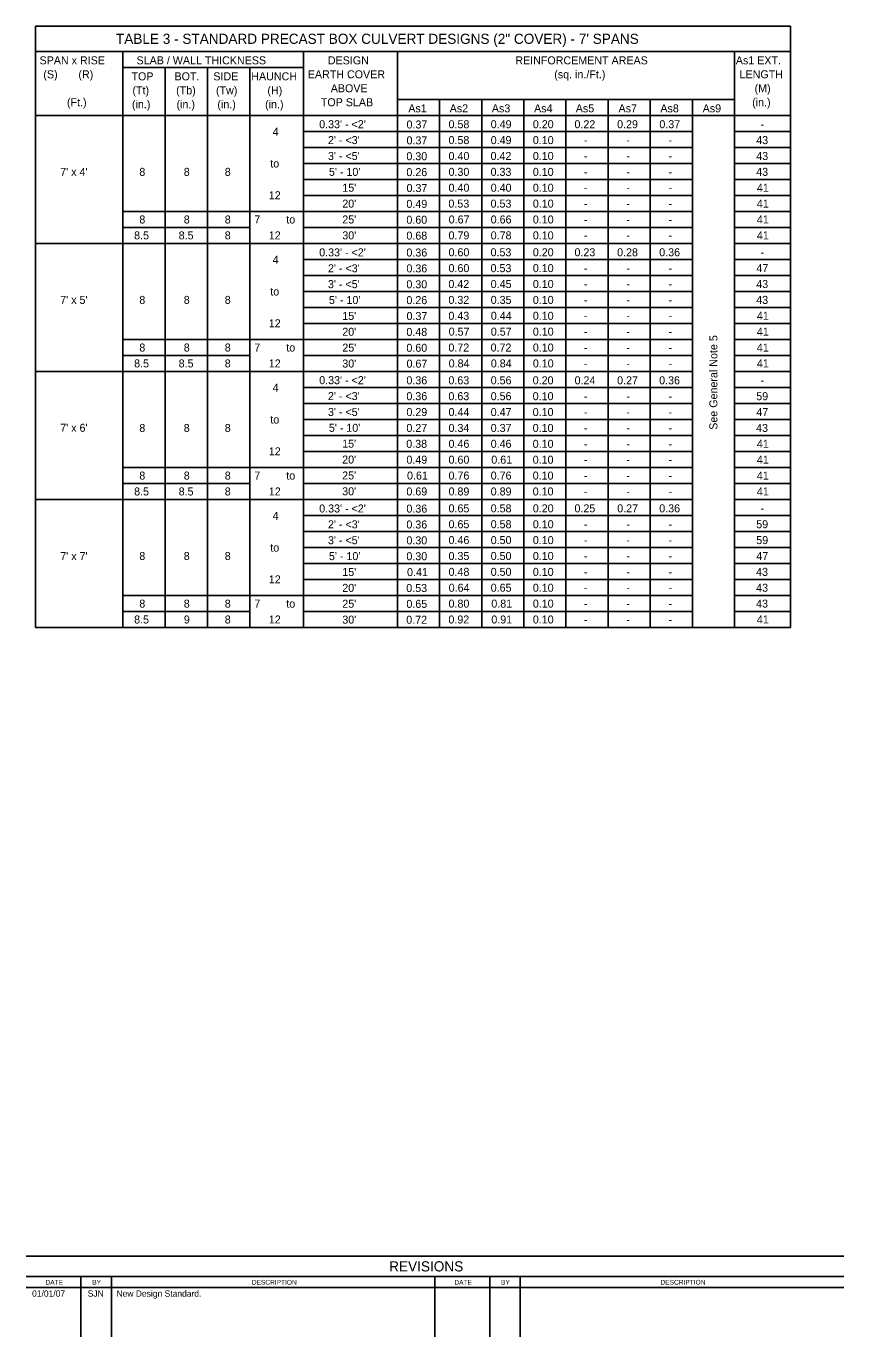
# Model space of a CAD drawing. Extents: x 10342.77 to 10344.98, y 76399.47 to 76400.59.
# Drawn here: x 10342.77 to 10343.414, y 76399.468 to 76400.5 of the extents above; entities that cross this region are included whole.
import ezdxf

# ---------------------------------------------------------------- set-up
doc = ezdxf.new("R2010")
doc.units = 0
for name, color, linetype in [('AdhocPoint_dp', 7, 'Continuous'), ('Border', 7, 'Continuous'), ('PlotBorder_dp', 7, 'Continuous')]:
    doc.layers.add(name, color=color, linetype=linetype)

msp = doc.modelspace()

# ---------------------------------------------------------------- linework, layer by layer
at = {"layer": 'Border'}
for p, q in [((10343.4138, 76399.5314), (10342.7697, 76399.5314)), ((10343.4138, 76399.5153), (10342.7697, 76399.5153)), ((10342.8127, 76399.5153), (10342.8127, 76399.468)), ((10342.8369, 76399.5153), (10342.8369, 76399.468)), ((10343.0917, 76399.5153), (10343.0917, 76399.468)), ((10343.1348, 76399.5153), (10343.1348, 76399.468)), ((10343.1589, 76399.5153), (10343.1589, 76399.468)), ((10342.7697, 76399.5068), (10343.4138, 76399.5068))]:
    msp.add_line(p, q, dxfattribs=at)
at = {"layer": 'PlotBorder_dp'}
for p, q in [((10342.7771, 76400.4997), (10343.3718, 76400.4997)), ((10342.7771, 76400.4997), (10342.7771, 76400.0263)), ((10343.3718, 76400.4997), (10343.3718, 76400.0263)), ((10342.7771, 76400.4798), (10343.3718, 76400.4798)), ((10342.8457, 76400.4798), (10342.8457, 76400.0263)), ((10342.9882, 76400.4798), (10342.9882, 76400.0263)), ((10343.0621, 76400.4798), (10343.0621, 76400.0263)), ((10343.3277, 76400.4798), (10343.3277, 76400.0263)), ((10342.8457, 76400.4672), (10342.9882, 76400.4672)), ((10342.8791, 76400.4672), (10342.8791, 76400.0263)), ((10342.9125, 76400.4672), (10342.9125, 76400.0263)), ((10342.9458, 76400.4672), (10342.9458, 76400.0263)), ((10343.0621, 76400.4421), (10343.3277, 76400.4421)), ((10343.0953, 76400.4421), (10343.0953, 76400.0263)), ((10343.1285, 76400.4421), (10343.1285, 76400.0263)), ((10343.1617, 76400.4421), (10343.1617, 76400.0263)), ((10343.1949, 76400.4421), (10343.1949, 76400.0263)), ((10343.2281, 76400.4421), (10343.2281, 76400.0263)), ((10343.2281, 76400.4421), (10343.2281, 76400.0263)), ((10343.2613, 76400.4421), (10343.2613, 76400.0263)), ((10343.2945, 76400.4421), (10343.2945, 76400.0263)), ((10342.7771, 76400.4295), (10343.3718, 76400.4295)), ((10342.9882, 76400.4169), (10343.2945, 76400.4169)), ((10343.3277, 76400.4169), (10343.3718, 76400.4169)), ((10342.9882, 76400.4043), (10343.2945, 76400.4043)), ((10343.3277, 76400.4043), (10343.3718, 76400.4043)), ((10342.9882, 76400.3917), (10343.2945, 76400.3917)), ((10343.3277, 76400.3917), (10343.3718, 76400.3917)), ((10342.9882, 76400.3791), (10343.2945, 76400.3791)), ((10343.3277, 76400.3791), (10343.3718, 76400.3791)), ((10342.9882, 76400.3665), (10343.2945, 76400.3665)), ((10343.3277, 76400.3665), (10343.3718, 76400.3665)), ((10342.9882, 76400.3539), (10342.8457, 76400.3539)), ((10342.9882, 76400.3539), (10343.2945, 76400.3539)), ((10343.3277, 76400.3539), (10343.3718, 76400.3539)), ((10342.9458, 76400.3413), (10342.8457, 76400.3413)), ((10342.9882, 76400.3413), (10343.2945, 76400.3413)), ((10343.3277, 76400.3413), (10343.3718, 76400.3413)), ((10342.7771, 76400.3287), (10343.2945, 76400.3287)), ((10342.9888, 76400.3287), (10343.061, 76400.3287)), ((10343.3277, 76400.3287), (10343.3718, 76400.3287)), ((10342.9882, 76400.3161), (10343.2945, 76400.3161)), ((10343.3277, 76400.3161), (10343.3718, 76400.3161)), ((10342.9882, 76400.3035), (10343.2945, 76400.3035)), ((10343.3277, 76400.3035), (10343.3718, 76400.3035)), ((10342.9882, 76400.2909), (10343.2945, 76400.2909)), ((10343.3277, 76400.2909), (10343.3718, 76400.2909)), ((10342.9882, 76400.2783), (10343.2945, 76400.2783)), ((10343.3277, 76400.2783), (10343.3718, 76400.2783)), ((10342.9882, 76400.2657), (10343.2945, 76400.2657)), ((10343.3277, 76400.2657), (10343.3718, 76400.2657)), ((10342.9882, 76400.2531), (10342.8457, 76400.2531)), ((10342.9882, 76400.2531), (10343.2945, 76400.2531)), ((10343.3277, 76400.2531), (10343.3718, 76400.2531)), ((10342.9458, 76400.2405), (10342.8457, 76400.2405)), ((10342.9882, 76400.2405), (10343.2945, 76400.2405)), ((10342.9888, 76400.2405), (10343.061, 76400.2405)), ((10343.3277, 76400.2405), (10343.3718, 76400.2405)), ((10342.7771, 76400.2279), (10343.2945, 76400.2279)), ((10343.3277, 76400.2279), (10343.3718, 76400.2279)), ((10342.9882, 76400.2153), (10343.2945, 76400.2153)), ((10343.3277, 76400.2153), (10343.3718, 76400.2153)), ((10342.9882, 76400.2027), (10343.2945, 76400.2027)), ((10343.3277, 76400.2027), (10343.3718, 76400.2027)), ((10342.9882, 76400.1901), (10343.2945, 76400.1901)), ((10343.3277, 76400.1901), (10343.3718, 76400.1901)), ((10342.9882, 76400.1775), (10343.2945, 76400.1775)), ((10343.3277, 76400.1775), (10343.3718, 76400.1775)), ((10342.9882, 76400.1649), (10343.2945, 76400.1649)), ((10343.3277, 76400.1649), (10343.3718, 76400.1649)), ((10342.9882, 76400.1523), (10342.8457, 76400.1523)), ((10342.9882, 76400.1523), (10343.2945, 76400.1523)), ((10343.3277, 76400.1523), (10343.3718, 76400.1523)), ((10342.9458, 76400.1397), (10342.8457, 76400.1397)), ((10342.9882, 76400.1397), (10343.2945, 76400.1397)), ((10343.3277, 76400.1397), (10343.3718, 76400.1397)), ((10342.7771, 76400.1271), (10343.2945, 76400.1271)), ((10343.3277, 76400.1271), (10343.3718, 76400.1271)), ((10342.9882, 76400.1145), (10343.2945, 76400.1145)), ((10343.3277, 76400.1145), (10343.3718, 76400.1145)), ((10342.9882, 76400.1019), (10343.2945, 76400.1019)), ((10343.3277, 76400.1019), (10343.3718, 76400.1019)), ((10342.9882, 76400.0893), (10343.2945, 76400.0893)), ((10343.3277, 76400.0893), (10343.3718, 76400.0893)), ((10342.9882, 76400.0767), (10343.2945, 76400.0767)), ((10343.3277, 76400.0767), (10343.3718, 76400.0767)), ((10342.9882, 76400.0641), (10343.2945, 76400.0641)), ((10343.3277, 76400.0641), (10343.3718, 76400.0641)), ((10342.9882, 76400.0515), (10342.8457, 76400.0515)), ((10342.9882, 76400.0515), (10343.2945, 76400.0515)), ((10343.3277, 76400.0515), (10343.3718, 76400.0515)), ((10342.9458, 76400.0389), (10342.8457, 76400.0389)), ((10342.9882, 76400.0389), (10343.2945, 76400.0389)), ((10343.3277, 76400.0389), (10343.3718, 76400.0389)), ((10342.7771, 76400.0263), (10343.3718, 76400.0263)), ((10342.9828, 76400.0263), (10343.3592, 76400.0263)), ((10342.9888, 76400.0263), (10343.061, 76400.0263))]:
    msp.add_line(p, q, dxfattribs=at)

# ---------------------------------------------------------------- texts
at = {"layer": 'AdhocPoint_dp'}
for s, height, p in [('TABLE 3 - STANDARD PRECAST BOX CULVERT DESIGNS (2" COVER) - 7\' SPANS', 0.008, (10342.8404, 76400.4858)), ('SLAB / WALL THICKNESS', 0.0063, (10342.8566, 76400.4697)), ('As1', 0.0063, (10343.0707, 76400.4319)), ('As2', 0.0063, (10343.1033, 76400.4319)), ('As3', 0.0063, (10343.1365, 76400.4319)), ('As4', 0.0063, (10343.1698, 76400.4319)), ('As5', 0.0063, (10343.2026, 76400.4319)), ('As7', 0.0063, (10343.2363, 76400.4319)), ('As8', 0.0063, (10343.2693, 76400.4319)), ('As9', 0.0063, (10343.3026, 76400.4319)), ('REVISIONS', 0.00802, (10343.0556, 76399.5194)), ('BY', 0.00375, (10342.8217, 76399.509)), ('BY', 0.00375, (10343.1437, 76399.509)), ('01/01/07', 0.005, (10342.7743, 76399.4995)), ('SJN', 0.005, (10342.8181, 76399.4995)), ('New Design Standard.', 0.005, (10342.8408, 76399.4995))]:
    msp.add_text(s, height=height, dxfattribs=at).set_placement(p)
for s, height, rotation, p in [('See General Note 5', 0.0063, 90, (10343.3142, 76400.182)), ('DATE', 0.00374, 359.8693, (10342.7849, 76399.509)), ('DESCRIPTION', 0.003752, 0.0498, (10342.9474, 76399.509)), ('DATE', 0.00374, 359.8693, (10343.107, 76399.509)), ('DESCRIPTION', 0.003752, 0.0498, (10343.2694, 76399.509))]:
    msp.add_text(s, height=height, rotation=rotation, dxfattribs=at).set_placement(p)
at = {"layer": 'PlotBorder_dp'}
for s, p in [('SPAN x RISE', (10342.7802, 76400.4697)), ('DESIGN', (10343.0073, 76400.4697)), ('REINFORCEMENT AREAS', (10343.155, 76400.4697)), ('(S)       (R)', (10342.7832, 76400.4587)), ('TOP', (10342.8526, 76400.4571)), ('BOT.', (10342.8865, 76400.4571)), ('SIDE', (10342.9171, 76400.4571)), ('HAUNCH', (10342.947, 76400.4571)), ('EARTH COVER', (10342.9915, 76400.4587)), ('(sq. in./Ft.)', (10343.1857, 76400.4587)), ('(Tt)', (10342.8534, 76400.4461)), ('(Tb)', (10342.8878, 76400.4461)), ('(Tw)', (10342.9192, 76400.4461)), ('(H)', (10342.9597, 76400.4461)), ('ABOVE', (10343.0096, 76400.4477)), ('(Ft.)', (10342.8018, 76400.4367)), ('(in.)', (10342.853, 76400.4351)), ('(in.)', (10342.8881, 76400.4351)), ('(in.)', (10342.9203, 76400.4351)), ('(in.)', (10342.9579, 76400.4351)), ('TOP SLAB', (10343.0018, 76400.4367)), ('4', (10342.9638, 76400.4135)), ("0.33' - <2'", (10343.0005, 76400.4194)), ('0.37', (10343.0693, 76400.4192)), ('0.58', (10343.1024, 76400.4194)), ('0.49', (10343.1356, 76400.4194)), ('0.20', (10343.1688, 76400.4194)), ('0.22', (10343.2016, 76400.4194)), ('0.29', (10343.2352, 76400.4194)), ('0.37', (10343.2685, 76400.4194)), ('-', (10343.3481, 76400.4194)), ("2' - <3'", (10343.0074, 76400.4069)), ('0.37', (10343.0693, 76400.4067)), ('0.58', (10343.1024, 76400.4069)), ('0.49', (10343.1356, 76400.4069)), ('0.10', (10343.1688, 76400.4069)), ('-', (10343.209, 76400.4069)), ('-', (10343.2425, 76400.4069)), ('-', (10343.2757, 76400.4069)), ('43', (10343.3448, 76400.4069)), ("3' - <5'", (10343.0074, 76400.3944)), ('0.30', (10343.0692, 76400.3942)), ('0.40', (10343.1024, 76400.3944)), ('0.42', (10343.1355, 76400.3944)), ('0.10', (10343.1688, 76400.3944)), ('43', (10343.3448, 76400.3944)), ("7' x 4'", (10342.7965, 76400.3819)), ('8', (10342.8588, 76400.3819)), ('8', (10342.8938, 76400.3819)), ('8', (10342.9261, 76400.3819)), ('to', (10342.962, 76400.3885)), ("5' - 10'", (10343.0082, 76400.3819)), ('0.26', (10343.0692, 76400.3817)), ('0.30', (10343.1024, 76400.3819)), ('0.33', (10343.1355, 76400.3819)), ('0.10', (10343.1688, 76400.3819)), ('-', (10343.209, 76400.3944)), ('-', (10343.2425, 76400.3944)), ('-', (10343.2757, 76400.3944)), ('43', (10343.3448, 76400.3819)), ('-', (10343.209, 76400.3819)), ('-', (10343.2425, 76400.3819)), ('-', (10343.2757, 76400.3819)), ('12', (10342.9608, 76400.3635)), ("15'", (10343.0187, 76400.3694)), ('0.37', (10343.0693, 76400.3692)), ('0.40', (10343.1024, 76400.3694)), ('0.40', (10343.1356, 76400.3694)), ('0.10', (10343.1688, 76400.3694)), ('-', (10343.209, 76400.3694)), ('-', (10343.2425, 76400.3694)), ('-', (10343.2757, 76400.3694)), ('41', (10343.3453, 76400.3694)), ("20'", (10343.0187, 76400.3569)), ('0.49', (10343.0692, 76400.3567)), ('0.53', (10343.1023, 76400.3569)), ('0.53', (10343.1355, 76400.3569)), ('0.10', (10343.1688, 76400.3569)), ('-', (10343.209, 76400.3569)), ('-', (10343.2425, 76400.3569)), ('-', (10343.2757, 76400.3569)), ('41', (10343.3453, 76400.3569)), ('8', (10342.8588, 76400.3444)), ('8', (10342.8938, 76400.3444)), ('8', (10342.9261, 76400.3444)), ('7 ', (10342.9494, 76400.3444)), ('to', (10342.9746, 76400.3444)), ("25'", (10343.0187, 76400.3444)), ('0.60', (10343.0692, 76400.3442)), ('0.67', (10343.1025, 76400.3444)), ('0.66', (10343.1356, 76400.3444)), ('0.10', (10343.1688, 76400.3444)), ('-', (10343.209, 76400.3444)), ('-', (10343.2425, 76400.3444)), ('-', (10343.2757, 76400.3444)), ('41', (10343.3453, 76400.3444)), ('8.5', (10342.8547, 76400.3319)), ('8.5', (10342.8898, 76400.3319)), ('8', (10342.9261, 76400.3319)), ('12', (10342.9608, 76400.3319)), ("30'", (10343.0187, 76400.3319)), ('0.68', (10343.0692, 76400.3317)), ('0.79', (10343.1024, 76400.3319)), ('0.78', (10343.1356, 76400.3319)), ('0.10', (10343.1688, 76400.3319)), ('41', (10343.3453, 76400.3319)), ('-', (10343.209, 76400.3319)), ('-', (10343.2425, 76400.3319)), ('-', (10343.2757, 76400.3319)), ('4', (10342.9638, 76400.3127)), ("0.33' - <2'", (10343.0005, 76400.3185)), ('0.36', (10343.0692, 76400.3184)), ('0.60', (10343.1024, 76400.3186)), ('0.53', (10343.1355, 76400.3186)), ('0.20', (10343.1688, 76400.3186)), ('0.23', (10343.2016, 76400.3186)), ('0.28', (10343.2352, 76400.3186)), ('0.36', (10343.2684, 76400.3186)), ('-', (10343.3481, 76400.3186)), ("2' - <3'", (10343.0074, 76400.306)), ('0.36', (10343.0692, 76400.3059)), ('0.60', (10343.1024, 76400.3061)), ('0.53', (10343.1355, 76400.3061)), ('0.10', (10343.1688, 76400.3061)), ('-', (10343.209, 76400.3061)), ('-', (10343.2425, 76400.3061)), ('-', (10343.2757, 76400.3061)), ('47', (10343.3449, 76400.3061)), ("3' - <5'", (10343.0074, 76400.2935)), ('0.30', (10343.0692, 76400.2934)), ('0.42', (10343.1023, 76400.2936)), ('0.45', (10343.1356, 76400.2936)), ('0.10', (10343.1688, 76400.2936)), ('-', (10343.209, 76400.2936)), ('-', (10343.2425, 76400.2936)), ('-', (10343.2757, 76400.2936)), ('43', (10343.3448, 76400.2936)), ("7' x 5'", (10342.7965, 76400.2811)), ('8', (10342.8588, 76400.2811)), ('8', (10342.8938, 76400.2811)), ('8', (10342.9261, 76400.2811)), ('to', (10342.962, 76400.2877)), ("5' - 10'", (10343.0082, 76400.281)), ('0.26', (10343.0692, 76400.2809)), ('0.32', (10343.1023, 76400.2811)), ('0.35', (10343.1356, 76400.2811)), ('0.10', (10343.1688, 76400.2811)), ('43', (10343.3448, 76400.2811)), ("15'", (10343.0187, 76400.2685)), ('0.37', (10343.0693, 76400.2684)), ('0.43', (10343.1023, 76400.2686)), ('0.44', (10343.1357, 76400.2686)), ('0.10', (10343.1688, 76400.2686)), ('-', (10343.209, 76400.2811)), ('-', (10343.2425, 76400.2811)), ('-', (10343.2757, 76400.2811)), ('41', (10343.3453, 76400.2686)), ('12', (10342.9608, 76400.2627)), ('-', (10343.209, 76400.2686)), ('-', (10343.2425, 76400.2686)), ('-', (10343.2757, 76400.2686)), ("20'", (10343.0187, 76400.256)), ('0.48', (10343.0692, 76400.2559)), ('0.57', (10343.1025, 76400.2561)), ('0.57', (10343.1357, 76400.2561)), ('0.10', (10343.1688, 76400.2561)), ('-', (10343.209, 76400.2561)), ('-', (10343.2425, 76400.2561)), ('-', (10343.2757, 76400.2561)), ('41', (10343.3453, 76400.2561)), ('8', (10342.8588, 76400.2436)), ('8', (10342.8938, 76400.2436)), ('8', (10342.9261, 76400.2436)), ('7 ', (10342.9494, 76400.2436)), ('to', (10342.9746, 76400.2436)), ("25'", (10343.0187, 76400.2435)), ('0.60', (10343.0692, 76400.2434)), ('0.72', (10343.1023, 76400.2436)), ('0.72', (10343.1355, 76400.2436)), ('0.10', (10343.1688, 76400.2436)), ('-', (10343.209, 76400.2436)), ('-', (10343.2425, 76400.2436)), ('-', (10343.2757, 76400.2436)), ('41', (10343.3453, 76400.2436)), ('8.5', (10342.8547, 76400.2311)), ('8.5', (10342.8898, 76400.2311)), ('8', (10342.9261, 76400.2311)), ('12', (10342.9608, 76400.2311)), ("30'", (10343.0187, 76400.231)), ('0.67', (10343.0693, 76400.2309)), ('0.84', (10343.1025, 76400.2311)), ('0.84', (10343.1357, 76400.2311)), ('0.10', (10343.1688, 76400.2311)), ('-', (10343.209, 76400.2311)), ('-', (10343.2425, 76400.2311)), ('-', (10343.2757, 76400.2311)), ('41', (10343.3453, 76400.2311)), ("0.33' - <2'", (10343.0005, 76400.2179)), ('0.36', (10343.0692, 76400.2178)), ('0.63', (10343.1023, 76400.2178)), ('0.56', (10343.1356, 76400.2178)), ('0.20', (10343.1687, 76400.2178)), ('0.24', (10343.2017, 76400.2178)), ('0.27', (10343.2352, 76400.2178)), ('0.36', (10343.2683, 76400.2178)), ('4', (10342.9638, 76400.2119)), ("2' - <3'", (10343.0074, 76400.2054)), ('-', (10343.3481, 76400.2178)), ('0.36', (10343.0692, 76400.2053)), ('0.63', (10343.1023, 76400.2053)), ('0.56', (10343.1356, 76400.2053)), ('0.10', (10343.1687, 76400.2053)), ('- ', (10343.209, 76400.2053)), ('-', (10343.2425, 76400.2053)), ('-', (10343.2757, 76400.2053)), ('59', (10343.3448, 76400.2053)), ('to', (10342.962, 76400.1869)), ("3' - <5'", (10343.0074, 76400.1929)), ('0.29', (10343.0692, 76400.1928)), ('0.44', (10343.1024, 76400.1928)), ('0.47', (10343.1356, 76400.1928)), ('0.10', (10343.1687, 76400.1928)), ('-', (10343.209, 76400.1928)), ('-', (10343.2425, 76400.1928)), ('-', (10343.2757, 76400.1928)), ('47', (10343.3449, 76400.1928)), ("7' x 6'", (10342.7965, 76400.1804)), ('8', (10342.8588, 76400.1803)), ('8', (10342.8938, 76400.1803)), ('8', (10342.9261, 76400.1803)), ("5' - 10'", (10343.0081, 76400.1804)), ('0.27', (10343.0692, 76400.1803)), ('0.34', (10343.1024, 76400.1803)), ('0.37', (10343.1356, 76400.1803)), ('0.10', (10343.1687, 76400.1803)), ('-', (10343.209, 76400.1803)), ('-', (10343.2425, 76400.1803)), ('-', (10343.2757, 76400.1803)), ('43', (10343.3447, 76400.1803)), ("15'", (10343.0186, 76400.1679)), ('0.38', (10343.0691, 76400.1678)), ('0.46', (10343.1024, 76400.1678)), ('0.46', (10343.1356, 76400.1678)), ('0.10', (10343.1687, 76400.1678)), ('-', (10343.209, 76400.1678)), ('-', (10343.2425, 76400.1678)), ('-', (10343.2757, 76400.1678)), ('41', (10343.3453, 76400.1678)), ('12', (10342.9608, 76400.1619)), ("20'", (10343.0186, 76400.1554)), ('0.49', (10343.0692, 76400.1553)), ('0.60', (10343.1024, 76400.1553)), ('0.61', (10343.1361, 76400.1553)), ('0.10', (10343.1687, 76400.1553)), ('41', (10343.3453, 76400.1553)), ('-', (10343.209, 76400.1553)), ('-', (10343.2425, 76400.1553)), ('-', (10343.2757, 76400.1553)), ('8', (10342.8588, 76400.1428)), ('8', (10342.8938, 76400.1428)), ('8', (10342.9261, 76400.1428)), ('7 ', (10342.9494, 76400.1428)), ('to', (10342.9746, 76400.1428)), ("25'", (10343.0186, 76400.1429)), ('0.61', (10343.0697, 76400.1428)), ('0.76', (10343.1024, 76400.1428)), ('0.76', (10343.1356, 76400.1428)), ('0.10', (10343.1687, 76400.1428)), ('-', (10343.209, 76400.1428)), ('-', (10343.2425, 76400.1428)), ('-', (10343.2757, 76400.1428)), ('41', (10343.3453, 76400.1428)), ('8.5', (10342.8547, 76400.1303)), ('8.5', (10342.8898, 76400.1303)), ('8', (10342.9261, 76400.1303)), ('12', (10342.9608, 76400.1303)), ("30'", (10343.0186, 76400.1304)), ('0.69', (10343.0692, 76400.1303)), ('0.89', (10343.1024, 76400.1303)), ('0.89', (10343.1356, 76400.1303)), ('0.10', (10343.1687, 76400.1303)), ('-', (10343.209, 76400.1303)), ('-', (10343.2425, 76400.1303)), ('-', (10343.2757, 76400.1303)), ('41', (10343.3453, 76400.1303)), ("0.33' - <2'", (10343.0005, 76400.1169)), ('0.36', (10343.0692, 76400.1168)), ('0.65', (10343.1024, 76400.117)), ('0.58', (10343.1356, 76400.117)), ('0.20', (10343.1688, 76400.117)), ('0.25', (10343.2016, 76400.117)), ('0.27', (10343.2353, 76400.117)), ('0.36', (10343.2684, 76400.117)), ('-', (10343.3481, 76400.117)), ('4', (10342.9638, 76400.1111)), ("2' - <3'", (10343.0074, 76400.1044)), ('0.36', (10343.0692, 76400.1043)), ('0.65', (10343.1024, 76400.1045)), ('0.58', (10343.1356, 76400.1045)), ('0.10', (10343.1688, 76400.1045)), ('59', (10343.3448, 76400.1045)), ("3' - <5'", (10343.0074, 76400.0919)), ('0.30', (10343.0692, 76400.0918)), ('0.46', (10343.1024, 76400.092)), ('0.50', (10343.1356, 76400.092)), ('0.10', (10343.1688, 76400.092)), ('-', (10343.209, 76400.1045)), ('-', (10343.2425, 76400.1045)), ('-', (10343.2757, 76400.1045)), ('59', (10343.3448, 76400.092)), ('to', (10342.962, 76400.0861)), ('-', (10343.209, 76400.092)), ('-', (10343.2425, 76400.092)), ('-', (10343.2757, 76400.092)), ("7' x 7'", (10342.7965, 76400.0794)), ('8', (10342.8588, 76400.0795)), ('8', (10342.8938, 76400.0795)), ('8', (10342.9261, 76400.0795)), ("5' - 10'", (10343.0082, 76400.0794)), ('0.30', (10343.0692, 76400.0793)), ('0.35', (10343.1024, 76400.0795)), ('0.50', (10343.1356, 76400.0795)), ('0.10', (10343.1688, 76400.0795)), ('-', (10343.209, 76400.0795)), ('-', (10343.2425, 76400.0795)), ('-', (10343.2757, 76400.0795)), ('47', (10343.3449, 76400.0795)), ('12', (10342.9608, 76400.0611)), ("15'", (10343.0187, 76400.0669)), ('0.41', (10343.0697, 76400.0668)), ('0.48', (10343.1024, 76400.067)), ('0.50', (10343.1356, 76400.067)), ('0.10', (10343.1688, 76400.067)), ('-', (10343.209, 76400.067)), ('-', (10343.2425, 76400.067)), ('-', (10343.2757, 76400.067)), ('43', (10343.3447, 76400.067)), ("20'", (10343.0187, 76400.0544)), ('0.53', (10343.0691, 76400.0543)), ('0.64', (10343.1025, 76400.0545)), ('0.65', (10343.1356, 76400.0545)), ('0.10', (10343.1688, 76400.0545)), ('-', (10343.209, 76400.0545)), ('-', (10343.2425, 76400.0545)), ('-', (10343.2757, 76400.0545)), ('43', (10343.3447, 76400.0545)), ('8', (10342.8588, 76400.042)), ('8', (10342.8938, 76400.042)), ('8', (10342.9261, 76400.042)), ('7 ', (10342.9494, 76400.042)), ('to', (10342.9746, 76400.042)), ("25'", (10343.0187, 76400.0419)), ('0.65', (10343.0692, 76400.0418)), ('0.80', (10343.1024, 76400.042)), ('0.81', (10343.1361, 76400.042)), ('0.10', (10343.1688, 76400.042)), ('43', (10343.3447, 76400.042)), ('-', (10343.209, 76400.042)), ('-', (10343.2425, 76400.042)), ('-', (10343.2757, 76400.042)), ('8.5', (10342.8547, 76400.0295)), ('9', (10342.8939, 76400.0295)), ('8', (10342.9261, 76400.0295)), ('12', (10342.9608, 76400.0295)), ("30'", (10343.0187, 76400.0294)), ('0.72', (10343.0691, 76400.0293)), ('0.92', (10343.1023, 76400.0295)), ('0.91', (10343.1361, 76400.0295)), ('0.10', (10343.1688, 76400.0295)), ('-', (10343.209, 76400.0295)), ('-', (10343.2425, 76400.0295)), ('-', (10343.2757, 76400.0295)), ('41', (10343.3453, 76400.0295))]:
    msp.add_text(s, height=0.0063, dxfattribs=at).set_placement(p)
for s, p in [('As1 EXT.', (10343.3287, 76400.4697)), ('LENGTH', (10343.3317, 76400.4587)), ('(M)', (10343.3435, 76400.4477)), ('(in.)', (10343.3416, 76400.4367))]:
    msp.add_text(s, height=0.0063, rotation=360, dxfattribs=at).set_placement(p)

doc.saveas('drawing.dxf')
